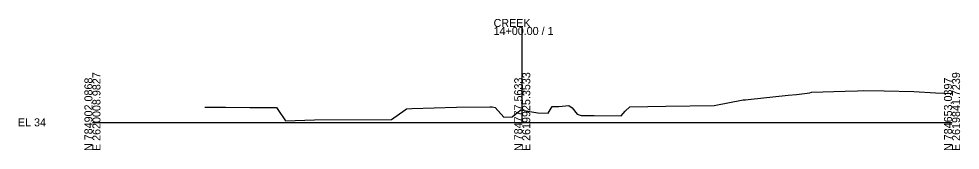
# Model space of a CAD drawing. Extents: x -26 to 303, y -10 to 5021.
# Drawn here: x -25.7 to 302.8, y 3490.3 to 3536.1 of the extents above; entities that cross this region are included whole.
import ezdxf

# ---------------------------------------------------------------- set-up
doc = ezdxf.new("R2010")
doc.units = 0
for name, color, linetype in [('RD_GPK_XS_Cell', 7, 'Continuous'), ('RD_XS_ExGround', 7, 'Continuous'), ('RD_XS_TX_Elev_EX', 7, 'Continuous')]:
    doc.layers.add(name, color=color, linetype=linetype)

msp = doc.modelspace()

# ---------------------------------------------------------------- linework, layer by layer
at = {"layer": 'RD_GPK_XS_Cell'}
for p, q in [((150, 3500), (150, 3533.27)), ((0, 3500), (150, 3500)), ((150, 3500), (300, 3500))]:
    msp.add_line(p, q, dxfattribs=at)
at = {"layer": 'RD_XS_ExGround'}
for p, q in [((228.9, 3508.03), (242.77, 3509.52)), ((242.77, 3509.52), (245.75, 3509.7)), ((245.75, 3509.7), (250.35, 3510.28)), ((250.35, 3510.28), (250.97, 3510.5)), ((250.97, 3510.5), (262.71, 3510.88)), ((262.71, 3510.88), (266.99, 3511.02)), ((266.99, 3511.02), (269.18, 3511.09)), ((269.18, 3511.09), (276.36, 3510.98)), ((276.36, 3510.98), (286.61, 3510.82)), ((286.61, 3510.82), (294.24, 3510.36)), ((294.24, 3510.36), (300, 3510.05)), ((159.37, 3503.76), (160.39, 3505.5)), ((160.39, 3505.5), (162.78, 3505.53)), ((162.78, 3505.53), (166.27, 3505.84)), ((166.27, 3505.84), (167.44, 3505.07)), ((185.9, 3503.94), (187.53, 3505.46)), ((187.53, 3505.46), (200.14, 3505.67)), ((200.14, 3505.67), (217.02, 3505.91)), ((217.02, 3505.91), (227.16, 3507.82)), ((227.16, 3507.82), (227.52, 3507.88)), ((227.52, 3507.88), (227.95, 3507.91)), ((227.95, 3507.91), (228.9, 3508.03)), ((39.18, 3505.3), (41.59, 3505.29)), ((41.59, 3505.29), (46.48, 3505.27)), ((46.48, 3505.27), (54.88, 3505.23)), ((54.88, 3505.23), (64.21, 3505.2)), ((64.21, 3505.2), (64.73, 3504.47)), ((64.73, 3504.47), (67.39, 3500.51)), ((104.36, 3500.98), (109.16, 3504.42)), ((109.16, 3504.42), (109.58, 3504.71)), ((109.58, 3504.71), (111.47, 3504.81)), ((111.47, 3504.81), (127.11, 3505.33)), ((127.11, 3505.33), (138.72, 3505.43)), ((138.72, 3505.43), (139.49, 3505.42)), ((139.49, 3505.42), (140.57, 3505.21)), ((140.57, 3505.21), (143.61, 3501.87)), ((146.54, 3501.98), (149.52, 3504.4)), ((149.52, 3504.4), (150, 3504.31)), ((150, 3504.31), (155.48, 3503.29)), ((155.48, 3503.29), (159, 3503.26)), ((159, 3503.26), (159.37, 3503.76)), ((167.44, 3505.07), (169.17, 3502.85)), ((169.17, 3502.85), (170.6, 3502.44)), ((170.6, 3502.44), (175.06, 3502.39)), ((175.06, 3502.39), (184.47, 3502.29)), ((184.47, 3502.29), (185.9, 3503.94)), ((67.39, 3500.51), (77.44, 3500.94)), ((77.44, 3500.94), (104.36, 3500.98)), ((143.61, 3501.87), (146.54, 3501.98))]:
    msp.add_line(p, q, dxfattribs=at)

# ---------------------------------------------------------------- texts
at = {"layer": 'RD_GPK_XS_Cell'}
for s, p in [('CREEK', (140, 3533.27)), ('14+00.00 / 1', (140, 3530.47)), ('EL 34', (-26, 3498.6))]:
    msp.add_text(s, height=2.8, dxfattribs=at).set_placement(p)
for s, p in [('N 784902.0868', (0, 3490)), ('E 2620008.9827', (2.8, 3490)), ('N 784777.5633', (150, 3490)), ('E 2619925.3533', (152.8, 3490)), ('N 784653.0397', (300, 3490)), ('E 2619841.7239', (302.8, 3490))]:
    msp.add_text(s, height=2.8, rotation=90, dxfattribs=at).set_placement(p)
at = {"layer": 'RD_XS_TX_Elev_EX'}
msp.add_text('38.31', height=0.8, rotation=90, dxfattribs=at).set_placement((150.7, 3509.31))

doc.saveas('drawing.dxf')
